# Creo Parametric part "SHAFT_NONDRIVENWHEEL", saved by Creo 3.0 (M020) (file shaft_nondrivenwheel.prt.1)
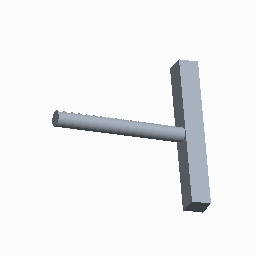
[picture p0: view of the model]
Units: millimeter Newton Second (mmNs); MM, TONNE, SECS

Created from: MMNS_PART_SOLID.PRT

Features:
  1. datum plane "RIGHT"
  2. datum plane "TOP"
  3. datum plane "FRONT"
  4. coordinate system
  5. sketch "Sketch 1"
  6. extrusion "Extrude 1"
  7. sketch "Sketch 2"
  8. extrusion "Extrude 2"

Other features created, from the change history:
  sketch "Sketch 1"
  extrusion "Extrude 1"
  sketch "Sketch 2"

Surfaces: 10 plane, 2 cylinder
